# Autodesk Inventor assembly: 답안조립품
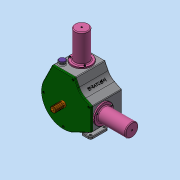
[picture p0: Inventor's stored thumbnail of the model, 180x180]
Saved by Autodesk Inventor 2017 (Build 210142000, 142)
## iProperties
Part Number: 답안조립품
Material: 일반
Document SubType Name: Assembly
Designer: MRC
Author: MRC
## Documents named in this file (13)
- C:\Users\MRC\Documents\Inventor\611109V1008\답안조립품.iam
- C:\Users\MRC\Documents\Inventor\611109V1008\611109V1008 (1)\본체.ipt
- C:\Users\MRC\Documents\Inventor\611109V1008\611109V1008 (1)\너트 M3.ipt
- C:\Users\MRC\Documents\Inventor\611109V1008\611109V1008 (1)\베어링 20 x 37 x 9.ipt
- C:\Users\MRC\Documents\Inventor\611109V1008\611109V1008 (1)\볼트 M3 x 12.ipt
- C:\Users\MRC\Documents\Inventor\611109V1008\611109V1008 (1)\실린더.ipt
- C:\Users\MRC\Documents\Inventor\611109V1008\611109V1008 (1)\앞커버.ipt
- C:\Users\MRC\Documents\Inventor\611109V1008\611109V1008 (1)\축.ipt
- C:\Users\MRC\Documents\Inventor\611109V1008\611109V1008 (1)\측정게이지.ipt
- C:\Users\MRC\Documents\Inventor\611109V1008\611109V1008 (1)\커넥팅로드 캡.ipt
- C:\Users\MRC\Documents\Inventor\611109V1008\611109V1008 (1)\커넥팅로드.ipt
- C:\Users\MRC\Documents\Inventor\611109V1008\611109V1008 (1)\피스톤 핀.ipt
- C:\Users\MRC\Documents\Inventor\611109V1008\611109V1008 (1)\피스톤.ipt
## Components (4 placed, 2 different names)
1. 피스톤 핀:1
2. 피스톤:1
3. 피스톤:2
4. 피스톤 핀:2
